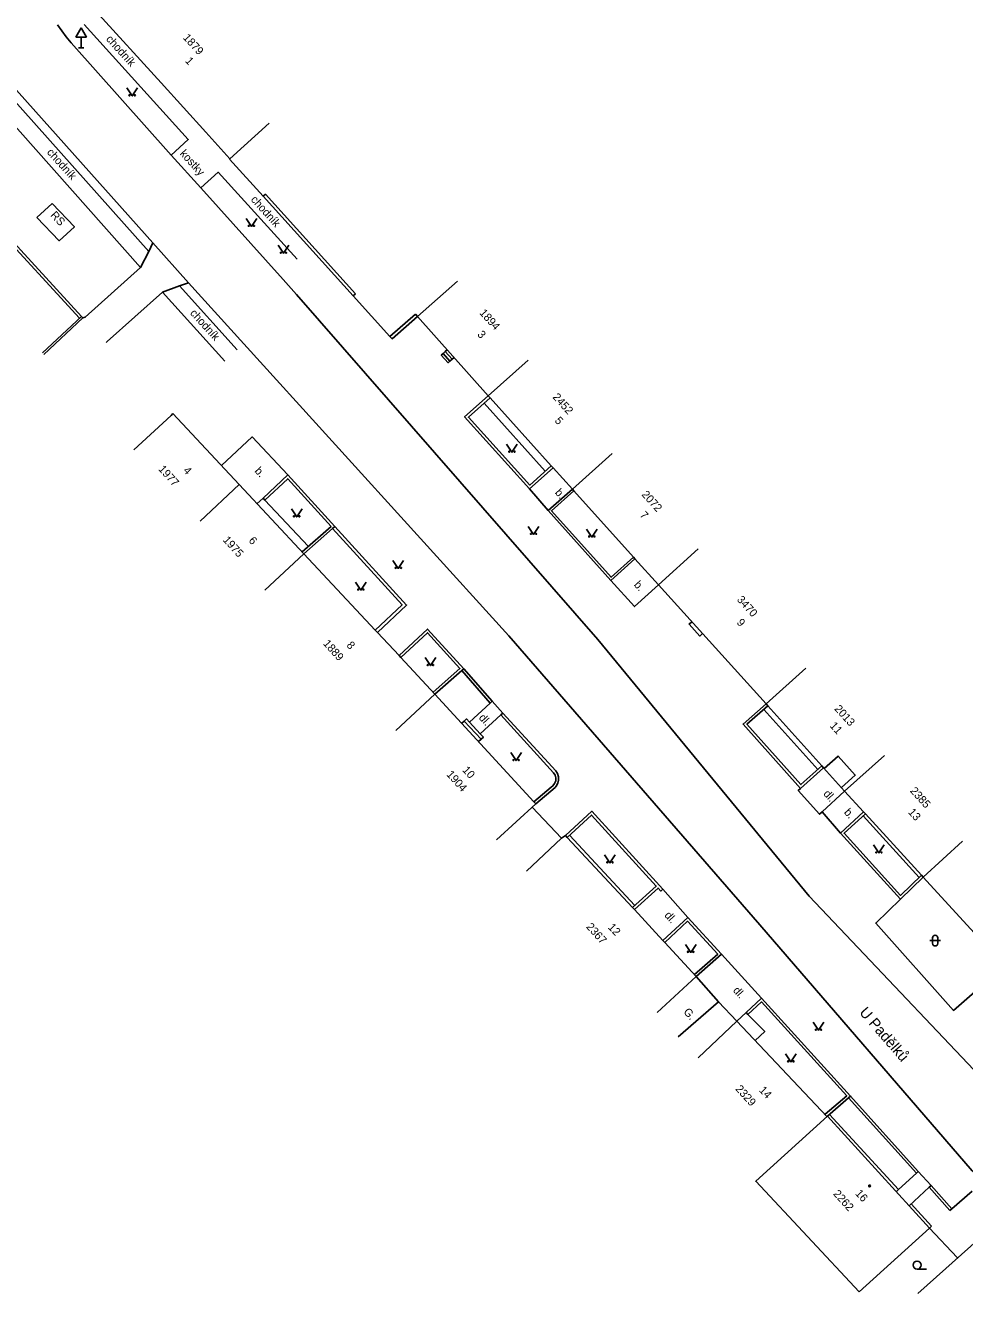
# Model space of a CAD drawing. Extents: x -584400 to -581602, y -1210894 to -1208793.
# Drawn here: x -582414.2 to -582326.3, y -1209583.8 to -1209464.9 of the extents above; entities that cross this region are included whole.
import ezdxf

# ---------------------------------------------------------------- set-up
doc = ezdxf.new("R2010")
doc.units = 0
for name, color, linetype in [('BUDOVY_MĚŘ', 7, 'Continuous'), ('NÁZVY_ULIC_TOK_SMĚR', 7, 'Continuous'), ('POMOC_POPIS', 7, 'Continuous'), ('ROZHRANÍ_PLOCH', 7, 'Continuous'), ('ZN_BUDOV', 7, 'Continuous'), ('ZN_DOPLŇKOVÉ', 7, 'Continuous'), ('ZN_KULTUR', 7, 'Continuous'), ('Č_POPIS_EVID', 7, 'Continuous')]:
    doc.layers.add(name, color=color, linetype=linetype)

msp = doc.modelspace()

# ---------------------------------------------------------------- linework, layer by layer
at = {"layer": 'BUDOVY_MĚŘ'}
for points in [[(-582397.34, -1209474.94), (-582401.53, -1209470.33), (-582407.67, -1209463.58)], [(-582395.07, -1209477.44), (-582391.4, -1209474.12)], [(-582397.34, -1209474.94), (-582395.07, -1209477.44)], [(-582395.11, -1209477.48), (-582395.07, -1209477.44)], [(-582377.5, -1209492.23), (-582373.77, -1209488.9)], [(-582377.5, -1209492.23), (-582370.88, -1209499.65)], [(-582370.88, -1209499.65), (-582367.15, -1209496.32)], [(-582370.88, -1209499.65), (-582370.71, -1209499.84), (-582364.97, -1209506.21), (-582364.8, -1209506.4), (-582362.99, -1209508.4)], [(-582400.41, -1209501.32), (-582400.59, -1209501.49), (-582404.07, -1209504.73)], [(-582400.41, -1209501.32), (-582394.21, -1209507.98)], [(-582362.99, -1209508.4), (-582359.28, -1209505.06)], [(-582394.21, -1209507.98), (-582397.87, -1209511.39)], [(-582394.21, -1209507.98), (-582388.15, -1209514.46)], [(-582362.99, -1209508.4), (-582362.86, -1209508.55), (-582357.26, -1209514.77), (-582357.13, -1209514.92), (-582354.93, -1209517.36)], [(-582388.15, -1209514.46), (-582391.8, -1209517.87)], [(-582388.15, -1209514.46), (-582381.47, -1209521.61), (-582381.26, -1209521.83), (-582379.23, -1209524), (-582379.06, -1209524.19), (-582375.87, -1209527.6)], [(-582354.93, -1209517.36), (-582351.21, -1209514.01)], [(-582354.93, -1209517.36), (-582344.84, -1209528.53)], [(-582344.84, -1209528.53), (-582341.13, -1209525.18)], [(-582375.87, -1209527.6), (-582379.52, -1209531.02)], [(-582375.87, -1209527.6), (-582366.59, -1209537.7), (-582366.42, -1209537.89), (-582370.1, -1209541.27)], [(-582344.84, -1209528.53), (-582344.67, -1209528.71), (-582339.63, -1209534.33), (-582339.46, -1209534.51), (-582337.49, -1209536.71)], [(-582337.49, -1209536.71), (-582333.77, -1209533.37)], [(-582337.49, -1209536.71), (-582335.72, -1209538.64), (-582335.55, -1209538.83), (-582330.3, -1209544.59), (-582330.13, -1209544.77)], [(-582363.64, -1209540.85), (-582364.01, -1209541.11), (-582367.29, -1209544.19)], [(-582363.64, -1209540.85), (-582363.47, -1209541.04), (-582357.36, -1209547.62), (-582357.19, -1209547.8), (-582354.51, -1209550.7), (-582354.34, -1209550.88), (-582351.39, -1209554.06)], [(-582330.13, -1209544.77), (-582326.44, -1209541.4)], [(-582330.13, -1209544.77), (-582322.61, -1209552.97)], [(-582351.39, -1209554.06), (-582355.05, -1209557.46)], [(-582351.39, -1209554.06), (-582349.3, -1209556.44), (-582353.07, -1209559.73)], [(-582339.15, -1209567.19), (-582347.58, -1209558.25), (-582351.22, -1209561.69)], [(-582339.1, -1209567.15), (-582345.82, -1209573.26), (-582336.13, -1209583.63)], [(-582329.53, -1209577.64), (-582339.1, -1209567.15)], [(-582329.53, -1209577.64), (-582336.13, -1209583.63)]]:
    msp.add_lwpolyline(points, dxfattribs=at)
at = {"layer": 'ROZHRANÍ_PLOCH'}
for points in [[(-582411.23, -1209464.88), (-582410.4, -1209466.01), (-582409.94, -1209466.59), (-582400.57, -1209477.09), (-582397.8, -1209480.16), (-582390.08, -1209488.74), (-582388.84, -1209490.16), (-582360.6, -1209522.5), (-582340.8, -1209546.53), (-582320.81, -1209567.67)], [(-582408.73, -1209464.85), (-582398.97, -1209475.64), (-582400.57, -1209477.09)], [(-582393.78, -1209494.78), (-582398.94, -1209489.07), (-582402.31, -1209485.33), (-582416.39, -1209469.54)], [(-582403.45, -1209487.63), (-582418.2, -1209471.05)], [(-582416.83, -1209470.28), (-582402.67, -1209486.12)], [(-582397.8, -1209480.16), (-582396.18, -1209478.7), (-582388.78, -1209486.84)], [(-582408.84, -1209492.36), (-582408.64, -1209492.3), (-582403.45, -1209487.63), (-582402.67, -1209486.12), (-582402.31, -1209485.33)], [(-582398.94, -1209489.07), (-582399.79, -1209489.34), (-582401.39, -1209489.93), (-582406.58, -1209494.58), (-582406.67, -1209494.66)], [(-582401.39, -1209489.93), (-582395.54, -1209496.42)], [(-582399.79, -1209489.34), (-582394.39, -1209495.36)], [(-582393.78, -1209494.78), (-582368.96, -1209522.14), (-582345.44, -1209549.23), (-582325.56, -1209572.29), (-582324.55, -1209573.35)], [(-582375.09, -1209495.68), (-582375.28, -1209495.85), (-582374.64, -1209496.56), (-582374.46, -1209496.4)], [(-582374.9, -1209495.51), (-582375.09, -1209495.68)], [(-582374.46, -1209496.4), (-582375.09, -1209495.68)], [(-582374.72, -1209495.35), (-582374.9, -1209495.51)], [(-582374.9, -1209495.51), (-582374.27, -1209496.23)], [(-582374.46, -1209496.4), (-582374.27, -1209496.23)], [(-582374.27, -1209496.23), (-582374.08, -1209496.06)], [(-582371.27, -1209500.34), (-582365.53, -1209506.71)], [(-582395.86, -1209506.2), (-582392.98, -1209503.51), (-582389.64, -1209507.07)], [(-582367, -1209508.37), (-582365.25, -1209510.41)], [(-582392.54, -1209509.77), (-582391.96, -1209509.24)], [(-582391.79, -1209509.42), (-582387.73, -1209513.76)], [(-582359.38, -1209516.95), (-582357.17, -1209519.41), (-582354.93, -1209517.36)], [(-582351.81, -1209520.82), (-582352.06, -1209521.05), (-582351.06, -1209522.17), (-582350.8, -1209521.93)], [(-582372.64, -1209530.23), (-582370.7, -1209528.45)], [(-582345.05, -1209529.04), (-582340, -1209534.66)], [(-582373.35, -1209530.34), (-582373.13, -1209530.14)], [(-582373.13, -1209530.14), (-582372.91, -1209529.94), (-582372.64, -1209530.23)], [(-582371.55, -1209531.84), (-582373.13, -1209530.14)], [(-582372.64, -1209530.23), (-582371.62, -1209531.33)], [(-582369.69, -1209529.55), (-582371.62, -1209531.33)], [(-582371.62, -1209531.33), (-582371.33, -1209531.64), (-582371.55, -1209531.84)], [(-582371.55, -1209531.84), (-582371.78, -1209532.05)], [(-582339.4, -1209534.59), (-582338.1, -1209533.42), (-582336.49, -1209535.2), (-582337.79, -1209536.37)], [(-582341.61, -1209536.44), (-582341.83, -1209536.64), (-582339.84, -1209538.86), (-582339.59, -1209538.63)], [(-582339.59, -1209538.63), (-582337.49, -1209536.71)], [(-582339.59, -1209538.63), (-582337.89, -1209540.63)], [(-582335.77, -1209539.03), (-582330.51, -1209544.79)], [(-582363.25, -1209540.83), (-582357.14, -1209547.42)], [(-582354.53, -1209545.9), (-582352.19, -1209548.55)], [(-582349.01, -1209551.99), (-582345.28, -1209556.1)], [(-582347.58, -1209558.25), (-582346.72, -1209557.45)], [(-582346.55, -1209557.63), (-582344.98, -1209559.24), (-582345.86, -1209560.08)], [(-582338.92, -1209566.99), (-582332.44, -1209574.04)], [(-582330.77, -1209572.5), (-582332.44, -1209574.04)], [(-582330.59, -1209572.34), (-582329.38, -1209573.65)], [(-582332.44, -1209574.04), (-582332.66, -1209574.24)], [(-582329.57, -1209573.81), (-582331.45, -1209575.55)], [(-582325.54, -1209574.2), (-582327.46, -1209575.85)], [(-582331.26, -1209575.39), (-582329.34, -1209577.47)], [(-582329.34, -1209577.47), (-582329.53, -1209577.64)]]:
    msp.add_lwpolyline(points, dxfattribs=at)
at = {"layer": 'ZN_BUDOV'}
msp.add_circle((-582335.15, -1209573.7), 0.0875, dxfattribs=at)
at = {"layer": 'ZN_DOPLŇKOVÉ'}
for p, q in [((-582409.02, -1209465.18), (-582409.52, -1209466.05)), ((-582409.52, -1209466.05), (-582408.52, -1209466.05)), ((-582409.02, -1209465.18), (-582408.52, -1209466.05)), ((-582409.02, -1209467.05), (-582409.02, -1209466.05)), ((-582409.27, -1209467.05), (-582408.77, -1209467.05))]:
    msp.add_line(p, q, dxfattribs=at)
for points in [[(-582426.86, -1209478.86), (-582423.73, -1209475.99), (-582417.04, -1209483.46), (-582408.98, -1209492.21)], [(-582409.16, -1209492.38), (-582417.22, -1209483.63), (-582423.75, -1209476.35), (-582426.69, -1209479.05)], [(-582395.11, -1209477.48), (-582391.96, -1209480.96)], [(-582413.15, -1209482.95), (-582411.71, -1209481.63)], [(-582413.15, -1209482.95), (-582411.08, -1209485.13), (-582409.64, -1209483.81), (-582411.71, -1209481.63)], [(-582383.53, -1209490.29), (-582391.96, -1209480.96), (-582391.74, -1209480.76)], [(-582391.74, -1209480.76), (-582383.3, -1209490.09)], [(-582383.53, -1209490.29), (-582383.3, -1209490.09)], [(-582383.53, -1209490.29), (-582380.09, -1209494.09)], [(-582408.98, -1209492.21), (-582412.64, -1209495.62)], [(-582408.98, -1209492.21), (-582408.84, -1209492.36), (-582412.5, -1209495.77)], [(-582377.7, -1209492), (-582380.09, -1209494.09)], [(-582377.7, -1209492), (-582377.5, -1209492.23), (-582379.89, -1209494.31), (-582380.09, -1209494.09)], [(-582370.88, -1209499.65), (-582373.09, -1209501.64), (-582367, -1209508.37), (-582364.8, -1209506.4)], [(-582370.71, -1209499.84), (-582372.73, -1209501.66), (-582366.98, -1209508.02), (-582364.97, -1209506.21)], [(-582391.96, -1209509.24), (-582389.64, -1209507.07), (-582385.25, -1209511.91), (-582385.47, -1209512.1)], [(-582388.31, -1209514.27), (-582385.6, -1209511.89), (-582389.66, -1209507.42), (-582391.79, -1209509.42)], [(-582362.99, -1209508.4), (-582365.25, -1209510.41), (-582359.38, -1209516.95), (-582357.13, -1209514.92)], [(-582362.86, -1209508.55), (-582364.96, -1209510.42), (-582359.37, -1209516.66), (-582357.26, -1209514.77)], [(-582391.96, -1209509.24), (-582391.79, -1209509.42)], [(-582385.47, -1209512.1), (-582388.15, -1209514.46)], [(-582381.47, -1209521.61), (-582378.95, -1209519.25), (-582385.47, -1209512.1)], [(-582385.25, -1209511.91), (-582378.53, -1209519.27), (-582381.26, -1209521.83)], [(-582379.23, -1209524), (-582376.56, -1209521.51), (-582373.17, -1209525.24), (-582373.36, -1209525.4)], [(-582376.04, -1209527.42), (-582373.53, -1209525.22), (-582376.57, -1209521.86), (-582379.06, -1209524.19)], [(-582373.36, -1209525.4), (-582375.87, -1209527.6)], [(-582373.36, -1209525.4), (-582370.7, -1209528.45), (-582370.51, -1209528.28)], [(-582373.17, -1209525.24), (-582370.51, -1209528.28)], [(-582369.51, -1209529.38), (-582370.51, -1209528.28)], [(-582344.84, -1209528.53), (-582347, -1209530.42), (-582341.61, -1209536.44), (-582339.46, -1209534.51)], [(-582344.67, -1209528.71), (-582346.65, -1209530.44), (-582341.59, -1209536.09), (-582339.63, -1209534.33)], [(-582369.69, -1209529.55), (-582369.51, -1209529.38), (-582364.56, -1209534.8), (-582364.4, -1209535.06), (-582364.31, -1209535.35), (-582364.3, -1209535.66), (-582364.37, -1209535.95), (-582364.51, -1209536.23), (-582364.6, -1209536.35), (-582366.42, -1209537.89)], [(-582369.69, -1209529.55), (-582364.75, -1209534.97), (-582364.61, -1209535.2), (-582364.55, -1209535.46), (-582364.56, -1209535.74), (-582364.66, -1209535.99), (-582364.82, -1209536.21), (-582364.98, -1209536.33), (-582366.59, -1209537.7)], [(-582364.01, -1209541.11), (-582366.75, -1209538.19)], [(-582363.64, -1209540.85), (-582361.18, -1209538.59), (-582354.53, -1209545.9)], [(-582335.72, -1209538.64), (-582337.89, -1209540.63), (-582332.27, -1209546.83), (-582330.13, -1209544.77)], [(-582357.36, -1209547.62), (-582355.14, -1209545.6), (-582361.2, -1209538.94), (-582363.47, -1209541.04)], [(-582335.55, -1209538.83), (-582337.54, -1209540.64), (-582332.25, -1209546.48), (-582330.3, -1209544.59)], [(-582357.19, -1209547.8), (-582354.97, -1209545.79), (-582354.72, -1209546.07), (-582354.53, -1209545.9)], [(-582332.27, -1209546.83), (-582334.58, -1209549.06), (-582327.29, -1209557.25), (-582324.8, -1209555.08)], [(-582354.51, -1209550.7), (-582352.19, -1209548.55), (-582349.01, -1209551.99), (-582351.39, -1209554.06)], [(-582351.55, -1209553.87), (-582349.37, -1209551.97), (-582352.21, -1209548.9), (-582354.34, -1209550.88)], [(-582347.58, -1209558.25), (-582349.3, -1209556.44)], [(-582346.72, -1209557.45), (-582345.28, -1209556.1), (-582336.93, -1209565.27), (-582337.12, -1209565.43)], [(-582339.33, -1209566.97), (-582337.29, -1209565.25), (-582345.29, -1209556.46), (-582346.55, -1209557.63)], [(-582346.72, -1209557.45), (-582346.55, -1209557.63)], [(-582337.12, -1209565.43), (-582339.1, -1209567.15)], [(-582330.77, -1209572.5), (-582337.12, -1209565.43)], [(-582336.93, -1209565.27), (-582330.59, -1209572.34)], [(-582330.77, -1209572.5), (-582330.59, -1209572.34)], [(-582329.38, -1209573.65), (-582329.57, -1209573.81)], [(-582327.65, -1209576.01), (-582329.57, -1209573.81)], [(-582329.38, -1209573.65), (-582327.46, -1209575.85)], [(-582327.65, -1209576.01), (-582327.46, -1209575.85)], [(-582326.95, -1209580.4), (-582329.53, -1209577.64)], [(-582324.3, -1209579.26), (-582324.8, -1209578.55), (-582330.63, -1209583.79)]]:
    msp.add_lwpolyline(points, dxfattribs=at)
at = {"layer": 'ZN_KULTUR'}
for p, q in [((-582329.51, -1209550.71), (-582328.51, -1209550.71)), ((-582329.26, -1209550.96), (-582329.26, -1209550.46)), ((-582328.76, -1209550.96), (-582328.76, -1209550.46)), ((-582330.7, -1209581.49), (-582329.83, -1209581.49))]:
    msp.add_line(p, q, dxfattribs=at)
for points in [[(-582404.73, -1209470.8), (-582404.23, -1209471.55), (-582403.73, -1209470.8)], [(-582393.56, -1209483.03), (-582393.06, -1209483.78), (-582392.56, -1209483.03)], [(-582390.56, -1209485.55), (-582390.06, -1209486.3), (-582389.56, -1209485.55)], [(-582369.16, -1209504.19), (-582368.66, -1209504.94), (-582368.16, -1209504.19)], [(-582389.32, -1209510.25), (-582388.82, -1209511), (-582388.32, -1209510.25)], [(-582367.13, -1209511.9), (-582366.63, -1209512.65), (-582366.13, -1209511.9)], [(-582361.67, -1209512.14), (-582361.17, -1209512.89), (-582360.67, -1209512.14)], [(-582379.8, -1209515.08), (-582379.3, -1209515.83), (-582378.8, -1209515.08)], [(-582383.31, -1209517.11), (-582382.81, -1209517.86), (-582382.31, -1209517.11)], [(-582376.79, -1209524.18), (-582376.29, -1209524.93), (-582375.79, -1209524.18)], [(-582368.77, -1209533.09), (-582368.27, -1209533.84), (-582367.77, -1209533.09)], [(-582334.78, -1209541.74), (-582334.28, -1209542.49), (-582333.78, -1209541.74)], [(-582359.98, -1209542.67), (-582359.48, -1209543.42), (-582358.98, -1209542.67)], [(-582352.41, -1209551.06), (-582351.91, -1209551.81), (-582351.41, -1209551.06)], [(-582340.44, -1209558.36), (-582339.94, -1209559.11), (-582339.44, -1209558.36)], [(-582343.03, -1209561.32), (-582342.53, -1209562.07), (-582342.03, -1209561.32)]]:
    msp.add_lwpolyline(points, dxfattribs=at)
for centre, radius in [((-582404.48, -1209471.5), 0.05), ((-582403.98, -1209471.5), 0.05), ((-582393.31, -1209483.73), 0.05), ((-582392.81, -1209483.73), 0.05), ((-582390.31, -1209486.25), 0.05), ((-582389.81, -1209486.25), 0.05), ((-582368.91, -1209504.89), 0.05), ((-582368.41, -1209504.89), 0.05), ((-582389.07, -1209510.95), 0.05), ((-582388.57, -1209510.95), 0.05), ((-582366.88, -1209512.6), 0.05), ((-582366.38, -1209512.6), 0.05), ((-582361.42, -1209512.84), 0.05), ((-582360.92, -1209512.84), 0.05), ((-582379.55, -1209515.78), 0.05), ((-582379.05, -1209515.78), 0.05), ((-582383.06, -1209517.81), 0.05), ((-582382.56, -1209517.81), 0.05), ((-582376.54, -1209524.88), 0.05), ((-582376.04, -1209524.88), 0.05), ((-582368.52, -1209533.79), 0.05), ((-582368.02, -1209533.79), 0.05), ((-582334.53, -1209542.44), 0.05), ((-582334.03, -1209542.44), 0.05), ((-582359.73, -1209543.37), 0.05), ((-582359.23, -1209543.37), 0.05), ((-582352.16, -1209551.76), 0.05), ((-582351.66, -1209551.76), 0.05), ((-582340.19, -1209559.06), 0.05), ((-582339.69, -1209559.06), 0.05), ((-582342.78, -1209562.02), 0.05), ((-582342.28, -1209562.02), 0.05), ((-582330.7, -1209581.11), 0.375)]:
    msp.add_circle(centre, radius, dxfattribs=at)
for centre, start, end in [((-582329.01, -1209550.46), 0, 180), ((-582329.01, -1209550.96), 180, 360)]:
    msp.add_arc(centre, 0.25, start, end, dxfattribs=at)

# ---------------------------------------------------------------- texts
at = {"layer": 'NÁZVY_ULIC_TOK_SMĚR'}
msp.add_text('U Padělků', height=1, rotation=310.7444, dxfattribs=at).set_placement((-582336.17, -1209557.47))
at = {"layer": 'POMOC_POPIS'}
for s, rotation, p in [('chodník', 312.0311, (-582406.73, -1209466.26)), ('chodník', 312.0311, (-582412.27, -1209476.87)), ('kostky', 312.0311, (-582399.81, -1209476.99)), ('chodník', 312.0311, (-582393.17, -1209481.3)), ('RS', 313.5174, (-582411.94, -1209482.78)), ('chodník', 312.0311, (-582398.86, -1209491.94)), ('b.', 313.0906, (-582392.81, -1209506.74)), ('b.', 312.0038, (-582364.68, -1209508.76)), ('b.', 312.0038, (-582357.28, -1209517.4)), ('dl.', 312.3875, (-582371.81, -1209529.86)), ('dl.', 311.9766, (-582339.54, -1209536.98)), ('b.', 311.9766, (-582337.6, -1209538.72)), ('dl.', 311.468, (-582354.42, -1209548.37)), ('dl.', 311.468, (-582348, -1209555.41)), ('G.', 312.3875, (-582352.64, -1209557.43))]:
    msp.add_text(s, height=0.75, rotation=rotation, dxfattribs=at).set_placement(p)
at = {"layer": 'Č_POPIS_EVID'}
for s, rotation, p in [('1879', 312.2812, (-582399.52, -1209466.13)), ('1', 312.2648, (-582399.31, -1209468.31)), ('1894', 312.0213, (-582371.75, -1209491.92)), ('3', 311.7192, (-582371.95, -1209493.94)), ('2452', 312.0213, (-582364.89, -1209499.81)), ('5', 312.0241, (-582364.7, -1209502.02)), ('1977', 312.0213, (-582401.82, -1209506.56)), ('4', 312.9517, (-582399.5, -1209506.7)), ('2072', 312.0213, (-582356.56, -1209508.94)), ('7', 312.0038, (-582356.73, -1209510.87)), ('1975', 312.0213, (-582395.78, -1209513.2)), ('6', 313.0906, (-582393.37, -1209513.27)), ('3470', 312.0213, (-582347.63, -1209518.79)), ('9', 312.0806, (-582347.65, -1209520.94)), ('1889', 312.0213, (-582386.39, -1209522.91)), ('8', 313.0586, (-582384.2, -1209523.08)), ('2013', 312.0213, (-582338.5, -1209529.02)), ('11', 311.9562, (-582338.93, -1209530.61)), ('1904', 312.0213, (-582374.84, -1209535.17)), ('10', 312.5621, (-582373.35, -1209534.77)), ('2385', 312.0213, (-582331.41, -1209536.71)), ('13', 312.3927, (-582331.59, -1209538.72)), ('2367', 312.0213, (-582361.75, -1209549.45)), ('12', 312.8606, (-582359.71, -1209549.5)), ('2329', 312.0213, (-582347.77, -1209564.64)), ('14', 313.35, (-582345.56, -1209564.77)), ('2262', 312.021, (-582338.61, -1209574.47)), ('16', 312.635, (-582336.55, -1209574.44))]:
    msp.add_text(s, height=0.75, rotation=rotation, dxfattribs=at).set_placement(p)

doc.saveas('drawing.dxf')
